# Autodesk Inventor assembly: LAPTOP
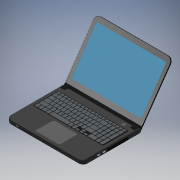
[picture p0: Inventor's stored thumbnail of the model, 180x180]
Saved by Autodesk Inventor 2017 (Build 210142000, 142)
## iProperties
Created: 2017-02
Part Number: LAPTOP
Document SubType Name: Assembly
Designer: Ali
Author: Ali
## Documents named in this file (4)
- C:\Users\Ali\Desktop\INVENTOR LIBRARY\LAPTOP\LAPTOP.iam
- C:\Users\Ali\Desktop\INVENTOR LIBRARY\LAPTOP\BOARD.ipt
- C:\Users\Ali\Desktop\INVENTOR LIBRARY\LAPTOP\KEYBOARD.ipt
- C:\Users\Ali\Desktop\INVENTOR LIBRARY\LAPTOP\MONITOR.ipt
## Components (3 placed, 3 different names)
1. BOARD:1 — Flush:1, Flush:2
2. KEYBOARD:1
3. MONITOR:1 — Flush:1
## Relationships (2: Flush 2)
- Flush:1: BOARD:1 ↔ MONITOR:1
- Flush:2: BOARD:1
